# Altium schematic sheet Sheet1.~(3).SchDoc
size A4; SheetNumber: 1; SheetTotal: 1; SPICEModelCacheJFKDNKES: <root> / <DocumentId>JFKDNKES</DocumentId> / <CacheFrame Number="0"> / <Model Name="2n3904" Kind="MDL"> / <Text>*2N3904 / *Si 310mW  40V 200mA 300MHz pkg:TO-92B 1,2,3 / .MODEL 2N3904 NPN(IS=1.4E-14 BF=300 VAF=100 IKF=0.025 ISE=3E-13 / + BR=7.5 RC=2.4 CJE=4.5E-12 TF=4E-10 CJC=3.5E-12 TR=2.1E-8 XTB=1.5 KF=9E-16 )</Text> / </Model> / </CacheFrame> / </root>
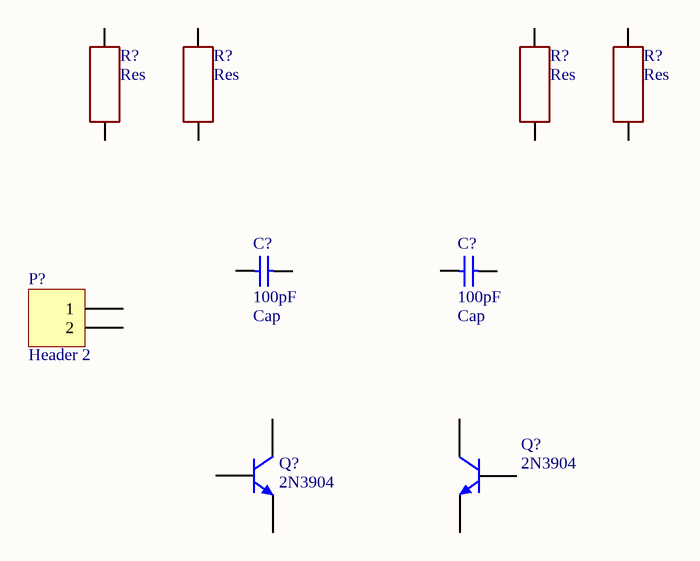
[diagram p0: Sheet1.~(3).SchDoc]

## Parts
(Parts that share a designator on the sheet are numbered #1, #2 ... from top to bottom, then left to right.)
C?#1  Cap  value 100pF  [RAD-0.3]
C?#2  Cap  value 100pF  [RAD-0.3]
P?  Header 2  [HDR1X2]
Q?#1  2N3904  [TO-92A]
Q?#2  2N3904  [TO-92A]
R?#1  Res  [Res 0805]
R?#2  Res  [Res 0805]
R?#3  Res  [Res 0805]
R?#4  Res  [Res 0805]

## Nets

Not connected (* = marked no-connect by the designer): C?#1 1 2; C?#2 1 2; P? 1 2; Q?#1 1(E) 2(B) 3(C); Q?#2 1(E) 2(B) 3(C); R?#1 1 2; R?#2 1 2; R?#3 1 2; R?#4 1 2

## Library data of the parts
C?#1 C?#2 = Cap: Capacitor
P? = Header 2: Header, 2-Pin
Q?#1 Q?#2 = 2N3904: NPN General Purpose Amplifier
